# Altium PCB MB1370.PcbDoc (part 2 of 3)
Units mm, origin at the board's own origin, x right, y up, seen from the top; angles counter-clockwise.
Board outline 166 x 117 mm, 4 copper layers (Top Layer, Signal Layer 1, Signal Layer 2, Bottom Layer), stack 1.614 mm thick; 79 components, 100 nets, 342 pads, 822 vias.
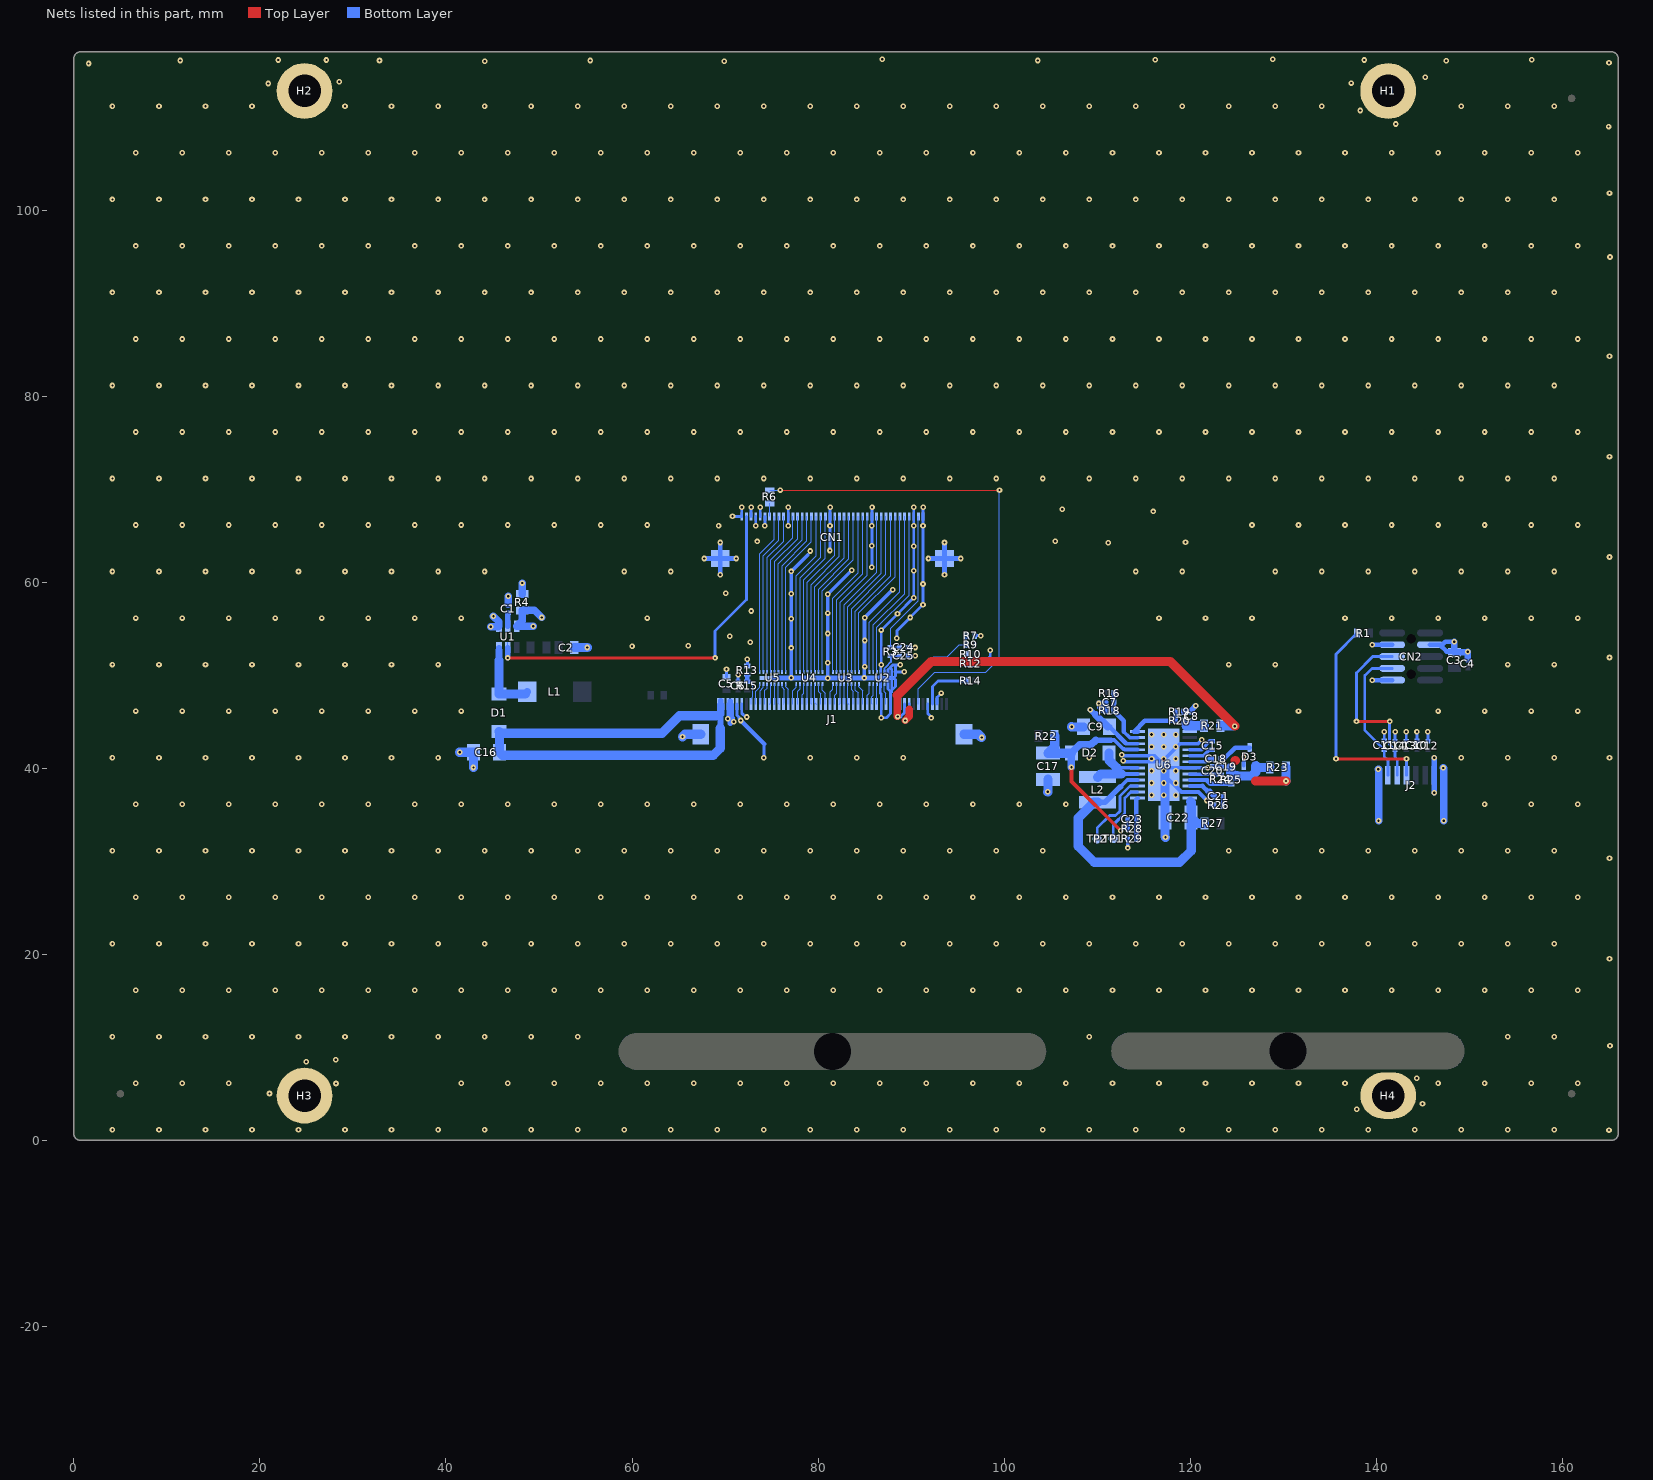
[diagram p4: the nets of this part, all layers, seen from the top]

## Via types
v1: diameter 0.6, hole 0.254, Top Layer to Bottom Layer, tented both sides, 804 vias
v2: diameter 0.6, hole 0.3, Top Layer to Bottom Layer, tented both sides, 18 vias

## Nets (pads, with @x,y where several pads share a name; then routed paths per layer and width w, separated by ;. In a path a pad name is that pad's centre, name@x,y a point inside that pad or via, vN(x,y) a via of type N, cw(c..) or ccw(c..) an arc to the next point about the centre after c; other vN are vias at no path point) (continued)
GND: C1.1 C2.1 C3.1 C4.2 C5.1 C6.1 C7.1 C8.1 C9.1 C10.1 C11.1 C12.1 C13.1 C14.1 C16.1 C17.1 C19.1 C20.1 C22.1 C24.1 C25.1 CN1.1 CN1.3 CN1.12 CN1.21 CN1.30 CN1.35 CN1.36 CN1.37 CN1.38 CN1.40 CN1.MT1 CN1.MT2 CN2.1 CN2.7 CN2.8 D3.2 H1.1 H2.1 H3.1 H4.1 J1.3 J1.13 J1.15 J1.46 J1.MT1 J1.MT2 J2.1 J2.MT1 J2.MT2 R4.1 R7.2 R12.2 R13.1 R18.1 R19.1 R26.1 R29.1 U1.4 U2.4 U2.6 U2.7 U2.8 U2.9 U2.10 U2.11 U2.13 U2.EP U3.EP U4.EP U5.EP U6.7 U6.8 U6.15 U6.19 U6.23 U6.EP | length 244.3
  Bottom Layer w0.3: v1@41.45,41.725 v1(41.461,41.714) ; C5.1@70.15,49.789 v1(70.15,50.65) ; v1(70.802,67.073) 70.812,67.063 CN1.40@71.79,67.063 71.79,68.04 v1(71.8,68.05) ; J1.46@71.29,46.889 71.29,45.685 71.5,45.475 71.5,45.3 v1(71.675,45.125) ; v1@71.375,50.075 v1(71.4,50.05) C6.1@71.4,49.289 ; R13.1@72.4,50.989 v1(72.4,51.725) ; CN1.38@72.79,67.063 72.79,68.04 v1(72.8,68.05) ; v1(73.28,66.075) 73.29,66.085 CN1.37@73.29,67.063 ; CN1.36@73.79,67.063 73.79,68.04 v1(73.8,68.05) ; v1@74.2,41.1 74.2,42.6 ; v1(74.28,66.075) 74.29,66.085 CN1.35@74.29,67.063 ; v1(76.78,66.075) 76.79,66.085 CN1.30@76.79,67.063 76.79,68.04 v1(76.8,68.05) ; v1(81.275,63.4) 81.28,63.405 v1(81.28,66.075) 81.29,66.085 CN1.21@81.29,67.063 81.29,68.04 v1(81.3,68.05) ; v1(85.775,61.6) 85.78,61.605 v1(85.78,66.075) 85.79,66.085 CN1.12@85.79,67.063 85.79,68.04 v1(85.8,68.05) ; U2.7@87.941,50.365 U2.7@87.925,50.349 ; v1(88.475,53.95) 88.475,54.775 v1(91.28,57.58) v1(91.28,66.075) 91.29,66.085 CN1.1@91.29,67.063 91.29,68.04 v1(91.3,68.05) ; v1(88.85,51.1) 88.4,51.1 ; v1(89.275,50.35) v1(89.275,50.35) U2.8@88.325,50.349 ; C25.1@89.65,52.075 v1(90.45,52.075) ; C24.1@89.65,52.975 v1(90.45,52.975) ; v1(90.3,68.05) 90.29,68.04 CN1.3@90.29,67.063 90.29,66.085 v1(90.28,66.075) v1(90.28,58.33) v1(88.54,56.59) v1(86.8,54.85) v1(86.8,51.125) 86.725,51.05 U2.4@86.725,50.349 86.725,49.899 U2.EP@86.925,49.699 ; J1.3@92.79,46.889 92.79,47.615 v1(93.25,48.075) ; R12.2@96.85,51.25 97.75,51.25 98.5,52 v1(98.5,52.675) ; R7.2@96.85,54.25 v1(97.5,54.25) ; C11.1@140.85,42.91 v1(140.85,43.925) ; C14.1@142.025,42.885 v1(142.025,43.9) ; C13.1@143.225,42.885 v1(143.225,43.9) ; C10.1@144.375,42.91 v1(144.375,43.925) ; C12.1@145.55,42.885 v1(145.55,43.9) ; U2.EP@86.925,49.699 86.725,49.499 U2.13@86.725,49.049 86.695,49.019 86.695,48.692 86.675,48.692 86.675,48.075 86.79,47.96 J1.15@86.79,46.889 86.79,45.435 v1(86.8,45.425) 87.35,45.425 87.79,45.865 J1.13@87.79,46.889 87.79,48.075 ; U2.EP@86.925,49.699 U2.EP@87.4,49.699 ; U2.EP@87.4,49.699 87.525,49.824 U2.6@87.525,50.349 87.525,50.591 87.72,50.786 ; U2.EP@87.4,49.699 U2.EP@87.476,49.699 ; U2.EP@87.476,49.699 87.525,49.65 U2.11@87.525,49.049 87.525,48.525 87.79,48.26 ; U2.EP@87.476,49.699 U2.EP@87.776,49.699 ; 87.72,50.786 87.925,50.581 U2.7@87.925,50.349 ; 87.72,50.786 87.72,50.795 88.025,51.1 88.4,51.1 ; U2.EP@87.776,49.699 87.925,49.55 U2.10@87.925,49.049 87.925,48.395 ; U2.EP@87.776,49.699 U2.EP@87.799,49.699 ; 87.79,48.075 87.925,48.21 87.925,48.395 ; 87.79,48.075 87.79,48.26 ; 87.79,48.26 87.925,48.395 ; U2.EP@87.799,49.699 87.925,49.825 U2.7@87.925,50.349 ; U2.EP@87.799,49.699 U2.EP@88.125,49.699 ; 87.925,48.395 88.325,48.795 U2.9@88.325,49.049 88.325,49.499 U2.EP@88.125,49.699 ; U2.EP@88.125,49.699 88.325,49.899 U2.8@88.325,50.349 ; U2.8@88.325,50.349 88.325,51.025 88.4,51.1
  Bottom Layer w0.4: v1(77.125,49.725) v1(77.125,61.15) 78.9,62.925 ; v1(81.05,49.65) 81.05,49.699 v1(81.05,58.7) v1(83.625,61.275) ; v1(84.975,49.7) 84.975,50.9 v1(85,50.925) v1(85,56.175) v1(88.025,59.2) ; 110.2,46.5 110.541,46.159 R18.1@110.9,46.159 ; v1(112.65,41.45) 112.766,41.334 U6.8@114.35,41.334 116.175,41.334 U6.EP@116.825,40.684 ; v1(112.8,40.8) 112.916,40.684 U6.7@114.35,40.684 U6.EP@116.825,40.684 ; v1(113.3,31.425) R29.1@113.3,32.434 ; v1(121.25,43.05) 120.834,42.634 U6.15@119.95,42.634 118.916,42.634 117.15,40.868 U6.EP@117.15,40.359 ; R26.1@122.6,35.989 122.336,35.989 120.891,37.434 U6.23@119.95,37.434 119.059,37.434 117.3,39.193 117.15,39.343 v2(117.15,39.709) U6.EP@117.15,40.359 ; C19.1@123.425,40.175 123.416,40.184 C20.1@122.425,40.184 122.275,40.034 v1(121.9,40.034) U6.19@119.95,40.034 117.475,40.034 117.3,40.209 U6.EP@117.15,40.359 ; D3.2@125.75,40.259 v1(125.75,41.2) ; U6.EP@116.825,40.684 U6.EP@117.15,40.359
  Bottom Layer w0.5: v1(67.763,62.538) CN1.MT2@69.49,62.538 ; v1(69.49,60.81) CN1.MT2@69.49,62.538 ; v1(69.49,64.265) CN1.MT2@69.49,62.538 ; v1(71.218,62.538) CN1.MT2@69.49,62.538 ; v1(71.675,45.125) 74.2,42.6 ; U5.EP@75.125,49.699 U4.EP@79.058,49.699 81.05,49.699 U3.EP@82.992,49.699 U2.EP@86.925,49.699 ; v1(91.862,62.538) CN1.MT1@93.59,62.538 ; v1(93.59,60.81) CN1.MT1@93.59,62.538 ; v1(93.59,64.265) CN1.MT1@93.59,62.538 ; v1(95.317,62.538) CN1.MT1@93.59,62.538 ; v1(139.59,49.46) CN2.1@141.715,49.46 ; v1(139.59,53.27) CN2.7@141.715,53.27 ; CN2.8@145.785,53.27 CN2.8@146.83,53.27 ; C3.1@148.4,52.55 147.55,52.55 CN2.8@146.83,53.27 ; v1(148.4,53.575) 147.4,53.575 147.095,53.27 CN2.8@146.83,53.27
  Bottom Layer w0.6: v1(110.175,46.95) 110.525,46.95 110.9,46.575 ; R18.1@110.9,46.159 110.9,46.575 ; C7.1@110.9,47.109 110.9,46.575 ; R19.1@119.325,46.084 120.1,46.084 C8.1@120.175,46.009 120.175,46.3 v1(120.6,46.725) ; v1(146.25,37.35) J2.1@146.25,39.235 v1(146.25,41.125)
  Bottom Layer w0.7: v1(148.4,53.575) 148.4,52.55 C3.1@148.4,52.475 149.825,52.475 v1(149.85,52.5) C4.2@149.85,51.675
  Bottom Layer w0.8: v1(44.8,55.2) 45.636,55.2 U1.4@45.7,55.264 45.7,55.75 v1(45.1,56.35) ; C1.1@46.7,57.614 v1(46.7,58.475) ; R4.1@48.2,58.714 v1(48.2,59.9) ; v1(140.225,39.9) 140.25,39.875 J2.MT2@140.25,37.135 v1(140.25,34.35) v1@140.275,34.325 ; v1(147.2,40.025) 147.25,39.975 J2.MT1@147.25,37.135 v1(147.25,34.35)
  Bottom Layer w1: v1(41.461,41.714) C16.1@42.95,41.714 v1(42.95,40.075) ; C2.1@53.8,52.964 55.189,52.964 v1(55.2,52.975) ; v1(65.425,43.375) 65.689,43.639 J1.MT1@67.39,43.639 ; J1.MT2@95.69,43.639 97.236,43.639 v1(97.575,43.3) ; v1(104.7,37.45) 104.725,37.475 C17.1@104.725,38.809 ; v1(107.25,44.45) 107.266,44.434 C9.1@108.525,44.434 ; U6.EP@117.3,40.209 117.3,39.193 C22.1@117.3,34.684 117.3,32.625 v1(117.35,32.575)
  other v1: 165.025,1.1 4.145,1.14 9.145,1.14 14.145,1.14 19.145,1.14 24.145,1.14 29.145,1.14 34.145,1.14 39.145,1.14 44.145,1.14 49.145,1.14 54.145,1.14 59.145,1.14 64.145,1.14 69.145,1.14 74.145,1.14 79.145,1.14 84.145,1.14 89.145,1.14 94.145,1.14 99.145,1.14 104.145,1.14 109.145,1.14 114.145,1.14 119.145,1.14 124.145,1.14 129.145,1.14 134.145,1.14 139.145,1.14 144.145,1.14 149.145,1.14 154.145,1.14 159.145,1.14 137.9,3.35 144.975,3.925 21.025,5.025 28.175,6.1 6.645,6.14 11.645,6.14 16.645,6.14 41.645,6.14 46.645,6.14 51.645,6.14 56.645,6.14 61.645,6.14 66.645,6.14 71.645,6.14 76.645,6.14 81.645,6.14 86.645,6.14 91.645,6.14 96.645,6.14 101.645,6.14 106.645,6.14 111.645,6.14 116.645,6.14 121.645,6.14 126.645,6.14 131.645,6.14 136.645,6.14 146.645,6.14 151.645,6.14 156.645,6.14 161.645,6.14 144.35,6.65 24.975,8.45 28.15,8.65 165.125,10.175 4.145,11.14 9.145,11.14 14.145,11.14 19.145,11.14 24.145,11.14 29.145,11.14 34.145,11.14 39.145,11.14 44.145,11.14 49.145,11.14 54.145,11.14 109.145,11.14 154.145,11.14 159.145,11.14 6.645,16.14 11.645,16.14 16.645,16.14 21.645,16.14 26.645,16.14 31.645,16.14 36.645,16.14 41.645,16.14 46.645,16.14 51.645,16.14 56.645,16.14 61.645,16.14 66.645,16.14 71.645,16.14 76.645,16.14 81.645,16.14 86.645,16.14 91.645,16.14 96.645,16.14 101.645,16.14 106.645,16.14 111.645,16.14 116.645,16.14 121.645,16.14 126.645,16.14 131.645,16.14 136.645,16.14 141.645,16.14 146.645,16.14 151.645,16.14 156.645,16.14 161.645,16.14 165.075,19.525 4.145,21.14 9.145,21.14 14.145,21.14 19.145,21.14 24.145,21.14 29.145,21.14 34.145,21.14 39.145,21.14 44.145,21.14 49.145,21.14 54.145,21.14 59.145,21.14 64.145,21.14 69.145,21.14 74.145,21.14 79.145,21.14 84.145,21.14 89.145,21.14 94.145,21.14 99.145,21.14 104.145,21.14 109.145,21.14 114.145,21.14 119.145,21.14 124.145,21.14 129.145,21.14 134.145,21.14 139.145,21.14 144.145,21.14 149.145,21.14 154.145,21.14 159.145,21.14 6.645,26.14 11.645,26.14 16.645,26.14 21.645,26.14 26.645,26.14 31.645,26.14 36.645,26.14 41.645,26.14 46.645,26.14 51.645,26.14 56.645,26.14 61.645,26.14 66.645,26.14 71.645,26.14 76.645,26.14 81.645,26.14 86.645,26.14 91.645,26.14 96.645,26.14 101.645,26.14 106.645,26.14 111.645,26.14 116.645,26.14 121.645,26.14 126.645,26.14 131.645,26.14 136.645,26.14 141.645,26.14 146.645,26.14 151.645,26.14 156.645,26.14 161.645,26.14 165.075,30.325 4.145,31.14 9.145,31.14 14.145,31.14 19.145,31.14 24.145,31.14 29.145,31.14 34.145,31.14 39.145,31.14 44.145,31.14 49.145,31.14 54.145,31.14 59.145,31.14 64.145,31.14 69.145,31.14 74.145,31.14 79.145,31.14 84.145,31.14 89.145,31.14 94.145,31.14 99.145,31.14 104.145,31.14 124.145,31.14 129.145,31.14 134.145,31.14 139.145,31.14 144.145,31.14 149.145,31.14 154.145,31.14 159.145,31.14 6.645,36.14 11.645,36.14 16.645,36.14 21.645,36.14 26.645,36.14 31.645,36.14 36.645,36.14 41.645,36.14 46.645,36.14 51.645,36.14 56.645,36.14 61.645,36.14 66.645,36.14 71.645,36.14 76.645,36.14 81.645,36.14 86.645,36.14 91.645,36.14 96.645,36.14 101.645,36.14 106.645,36.14 151.645,36.14 156.645,36.14 161.645,36.14 121.775,36.525 4.145,41.14 9.145,41.14 14.145,41.14 19.145,41.14 24.145,41.14 29.145,41.14 34.145,41.14 39.145,41.14 74.145,41.14 79.145,41.14 84.145,41.14 89.145,41.14 109.145,41.14 149.145,41.14 154.145,41.14 159.145,41.14 165.075,41.125 6.645,46.14 11.645,46.14 16.645,46.14 21.645,46.14 26.645,46.14 31.645,46.14 36.645,46.14 41.645,46.14 131.645,46.14 146.645,46.14 151.645,46.14 156.645,46.14 161.645,46.14 4.145,51.14 9.145,51.14 14.145,51.14 19.145,51.14 24.145,51.14 29.145,51.14 34.145,51.14 39.145,51.14 124.145,51.14 129.145,51.14 154.145,51.14 159.145,51.14 81.05,51.35 165.075,51.9 77.125,52.925 60,53.1 66.05,53.175 72.725,53.55 85,53.725 70.5,54.2 81.05,54.475 77.125,56.075 6.645,56.14 11.645,56.14 16.645,56.14 21.645,56.14 26.645,56.14 31.645,56.14 36.645,56.14 41.645,56.14 61.645,56.14 116.645,56.14 121.645,56.14 126.645,56.14 136.645,56.14 141.645,56.14 146.645,56.14 151.645,56.14 156.645,56.14 161.645,56.14 89.9,56.2 81.05,56.675 72.825,56.9 77.125,58.75 70.075,58.8 91.28,59.8 4.145,61.14 9.145,61.14 14.145,61.14 19.145,61.14 24.145,61.14 29.145,61.14 34.145,61.14 39.145,61.14 44.145,61.14 59.145,61.14 64.145,61.14 114.145,61.14 119.145,61.14 129.145,61.14 134.145,61.14 139.145,61.14 144.145,61.14 149.145,61.14 154.145,61.14 159.145,61.14 90.28,61.225 165.075,62.7 79.175,63.35 90.28,63.875 85.78,63.925 111.175,64.225 119.5,64.3 73.45,64.375 105.475,64.4 69.3,66.075 6.645,66.14 11.645,66.14 16.645,66.14 21.645,66.14 26.645,66.14 31.645,66.14 36.645,66.14 41.645,66.14 46.645,66.14 51.645,66.14 56.645,66.14 61.645,66.14 126.645,66.14 131.645,66.14 136.645,66.14 141.645,66.14 146.645,66.14 151.645,66.14 156.645,66.14 161.645,66.14 116.025,67.6 106.25,67.85 4.145,71.14 9.145,71.14 14.145,71.14 19.145,71.14 24.145,71.14 29.145,71.14 34.145,71.14 39.145,71.14 44.145,71.14 49.145,71.14 54.145,71.14 59.145,71.14 64.145,71.14 69.145,71.14 74.145,71.14 79.145,71.14 84.145,71.14 89.145,71.14 94.145,71.14 99.145,71.14 104.145,71.14 109.145,71.14 114.145,71.14 119.145,71.14 124.145,71.14 129.145,71.14 134.145,71.14 139.145,71.14 144.145,71.14 149.145,71.14 154.145,71.14 159.145,71.14 165.075,73.5 6.645,76.14 11.645,76.14 16.645,76.14 21.645,76.14 26.645,76.14 31.645,76.14 36.645,76.14 41.645,76.14 46.645,76.14 51.645,76.14 56.645,76.14 61.645,76.14 66.645,76.14 71.645,76.14 76.645,76.14 81.645,76.14 86.645,76.14 91.645,76.14 96.645,76.14 101.645,76.14 106.645,76.14 111.645,76.14 116.645,76.14 121.645,76.14 126.645,76.14 131.645,76.14 136.645,76.14 141.645,76.14 146.645,76.14 151.645,76.14 156.645,76.14 161.645,76.14 4.145,81.14 9.145,81.14 14.145,81.14 19.145,81.14 24.145,81.14 29.145,81.14 34.145,81.14 39.145,81.14 44.145,81.14 49.145,81.14 54.145,81.14 59.145,81.14 64.145,81.14 69.145,81.14 74.145,81.14 79.145,81.14 84.145,81.14 89.145,81.14 94.145,81.14 99.145,81.14 104.145,81.14 109.145,81.14 114.145,81.14 119.145,81.14 124.145,81.14 129.145,81.14 134.145,81.14 139.145,81.14 144.145,81.14 149.145,81.14 154.145,81.14 159.145,81.14 165.075,84.3 6.645,86.14 11.645,86.14 16.645,86.14 21.645,86.14 26.645,86.14 31.645,86.14 36.645,86.14 41.645,86.14 46.645,86.14 51.645,86.14 56.645,86.14 61.645,86.14 66.645,86.14 71.645,86.14 76.645,86.14 81.645,86.14 86.645,86.14 91.645,86.14 96.645,86.14 101.645,86.14 106.645,86.14 111.645,86.14 116.645,86.14 121.645,86.14 126.645,86.14 131.645,86.14 136.645,86.14 141.645,86.14 146.645,86.14 151.645,86.14 156.645,86.14 161.645,86.14 4.145,91.14 9.145,91.14 14.145,91.14 19.145,91.14 24.145,91.14 29.145,91.14 34.145,91.14 39.145,91.14 44.145,91.14 49.145,91.14 54.145,91.14 59.145,91.14 64.145,91.14 69.145,91.14 74.145,91.14 79.145,91.14 84.145,91.14 89.145,91.14 94.145,91.14 99.145,91.14 104.145,91.14 109.145,91.14 114.145,91.14 119.145,91.14 124.145,91.14 129.145,91.14 134.145,91.14 139.145,91.14 144.145,91.14 149.145,91.14 154.145,91.14 159.145,91.14 165.125,94.95 6.645,96.14 11.645,96.14 16.645,96.14 21.645,96.14 26.645,96.14 31.645,96.14 36.645,96.14 41.645,96.14 46.645,96.14 51.645,96.14 56.645,96.14 61.645,96.14 66.645,96.14 71.645,96.14 76.645,96.14 81.645,96.14 86.645,96.14 91.645,96.14 96.645,96.14 101.645,96.14 106.645,96.14 111.645,96.14 116.645,96.14 121.645,96.14 126.645,96.14 131.645,96.14 136.645,96.14 141.645,96.14 146.645,96.14 151.645,96.14 156.645,96.14 161.645,96.14 4.145,101.14 9.145,101.14 14.145,101.14 19.145,101.14 24.145,101.14 29.145,101.14 34.145,101.14 39.145,101.14 44.145,101.14 49.145,101.14 54.145,101.14 59.145,101.14 64.145,101.14 69.145,101.14 74.145,101.14 79.145,101.14 84.145,101.14 89.145,101.14 94.145,101.14 99.145,101.14 104.145,101.14 109.145,101.14 114.145,101.14 119.145,101.14 124.145,101.14 129.145,101.14 134.145,101.14 139.145,101.14 144.145,101.14 149.145,101.14 154.145,101.14 159.145,101.14 165.075,101.825 6.645,106.14 11.645,106.14 16.645,106.14 21.645,106.14 26.645,106.14 31.645,106.14 36.645,106.14 41.645,106.14 46.645,106.14 51.645,106.14 56.645,106.14 61.645,106.14 66.645,106.14 71.645,106.14 76.645,106.14 81.645,106.14 86.645,106.14 91.645,106.14 96.645,106.14 101.645,106.14 106.645,106.14 111.645,106.14 116.645,106.14 121.645,106.14 126.645,106.14 131.645,106.14 136.645,106.14 141.645,106.14 146.645,106.14 151.645,106.14 156.645,106.14 161.645,106.14 164.975,108.975 142.1,109.25 138.275,110.7 4.145,111.14 9.145,111.14 14.145,111.14 19.145,111.14 29.145,111.14 34.145,111.14 39.145,111.14 44.145,111.14 49.145,111.14 54.145,111.14 59.145,111.14 64.145,111.14 69.145,111.14 74.145,111.14 79.145,111.14 84.145,111.14 89.145,111.14 94.145,111.14 99.145,111.14 104.145,111.14 109.145,111.14 114.145,111.14 119.145,111.14 124.145,111.14 129.145,111.14 134.145,111.14 149.145,111.14 154.145,111.14 159.145,111.14 20.875,113.6 137.325,113.65 28.525,113.8 145.25,114.275 1.575,115.75 165.025,115.85 44.175,116 69.9,116 147.525,116.05 11.45,116.075 32.85,116.075 55.525,116.075 103.6,116.075 21.975,116.125 27.15,116.125 138.725,116.125 116.225,116.175 156.7,116.175 86.9,116.225 128.875,116.225
  other v2: 115.85,37.109 117.15,37.109 118.45,37.109 115.85,38.409 117.15,38.409 118.45,38.409 115.85,39.709 118.45,39.709 115.85,41.009 117.15,41.009 118.45,41.009 115.85,42.309 117.15,42.309 118.45,42.309 115.85,43.609 117.15,43.609 118.45,43.609
I2C_SCL: C14.2 CN2.5 J2.5 | length 19.5
  Top Layer w0.3: v1(137.875,45.025) v1(141.45,45.025)
  Bottom Layer w0.3: v1(137.875,45.025) 137.875,50.25 139.625,52 CN2.5@141.715,52 ; v1(141.45,45.025) 141.433,45.008 141.433,42.543 141.991,41.985 142.008,41.985 142.008,41.192 142.25,40.95 J2.5@142.25,39.235
I2C_SDA: C11.2 CN2.3 J2.6 | length 15
  Bottom Layer w0.3: J2.6@141.25,39.235 141.25,40.85 140.85,41.25 C11.2@140.85,42.01 140.833,42.01 138.775,44.068 138.775,49.975 139.53,50.73 CN2.3@141.715,50.73
LCD1_B0: J1.32 U4.14 | length 2.2
  Bottom Layer w0.12: J1.32@78.29,46.889 78.29,47.873 78.458,48.042 U4.14@78.458,49.049
LCD1_B1: J1.33 U4.15 | length 2.3
  Bottom Layer w0.12: J1.33@77.79,46.889 77.79,48.29 78.058,48.558 U4.15@78.058,49.049
LCD1_B2: J1.34 U4.16 | length 2.3
  Bottom Layer w0.12: J1.34@77.29,46.889 77.29,48.34 77.658,48.708 U4.16@77.658,49.049
LCD1_B3: J1.35 U5.9 | length 2.3
  Bottom Layer w0.12: U5.9@76.525,49.049 76.525,48.775 76.79,48.51 J1.35@76.79,46.889
LCD1_B4: J1.36 U5.10 | length 2.3
  Bottom Layer w0.12: U5.10@76.125,49.049 76.125,48.675 76.375,48.425 76.375,46.974 J1.36@76.29,46.889
LCD1_B5: J1.37 U5.11 | length 2.2
  Bottom Layer w0.12: U5.11@75.725,49.049 75.725,46.954 J1.37@75.79,46.889
LCD1_B6: J1.38 U5.12 | length 2.2
  Bottom Layer w0.12: J1.38@75.29,46.889 75.325,46.924 U5.12@75.325,49.049
LCD1_B7: J1.39 U5.13 | length 2.2
  Bottom Layer w0.12: J1.39@74.79,46.889 74.925,47.024 U5.13@74.925,49.049
LCD1_DCLK: J1.14 U2.12 | length 2.2
  Bottom Layer w0.12: U2.12@87.125,49.049 87.125,48.225 87.29,48.06 J1.14@87.29,46.889
LCD1_DE: J1.42 U5.16 | length 2.3
  Bottom Layer w0.12: J1.42@73.29,46.889 73.29,48.265 73.725,48.7 U5.16@73.725,49.049
LCD1_DITHB: J1.4 R14.2 | length 5.8
  Bottom Layer w0.3: J1.4@92.29,46.889 92.29,48.79 92.875,49.375 R14.2@95.95,49.375
LCD1_G0: J1.24 U3.14 | length 2.2
  Bottom Layer w0.12: J1.24@82.29,46.889 82.392,46.991 U3.14@82.392,49.049
LCD1_G1: J1.25 U3.15 | length 2.2
  Bottom Layer w0.12: J1.25@81.79,46.889 81.79,47.84 81.992,48.042 U3.15@81.992,49.049
LCD1_G2: J1.26 U3.16 | length 2.3
  Bottom Layer w0.12: J1.26@81.29,46.889 81.29,48.19 81.592,48.492 U3.16@81.592,49.049
LCD1_G3: J1.27 U4.9 | length 2.3
  Bottom Layer w0.12: U4.9@80.458,49.049 80.458,48.367 80.79,48.035 J1.27@80.79,46.889
LCD1_G4: J1.28 U4.10 | length 2.3
  Bottom Layer w0.12: U4.10@80.058,49.049 80.058,48.242 80.29,48.01 J1.28@80.29,46.889
LCD1_G5: J1.29 U4.11 | length 2.2
  Bottom Layer w0.12: U4.11@79.658,49.049 79.658,47.021 J1.29@79.79,46.889
LCD1_G6: J1.30 U4.12 | length 2.2
  Bottom Layer w0.12: U4.12@79.258,49.049 79.258,46.921 J1.30@79.29,46.889
LCD1_G7: J1.31 U4.13 | length 2.2
  Bottom Layer w0.12: J1.31@78.79,46.889 78.858,46.957 U4.13@78.858,49.049
LCD1_HSYNC: J1.40 U5.14 | length 2.3
  Bottom Layer w0.12: J1.40@74.29,46.889 74.29,48.365 74.525,48.6 U5.14@74.525,49.049
LCD1_MODE: J1.43 R13.2 R15.1 | length 3.7
  Bottom Layer w0.13: R15.1@72.4,49.289 72.761,49.289 73,49.05 73,47.661 72.79,47.451 J1.43@72.79,46.889
  Bottom Layer w0.5: R15.1@72.4,49.289 R13.2@72.4,50.089
LCD1_R0: J1.16 U2.14 | length 2.2
  Bottom Layer w0.12: J1.16@86.29,46.889 86.325,46.924 U2.14@86.325,49.049
LCD1_R1: J1.17 U2.15 | length 2.2
  Bottom Layer w0.12: J1.17@85.79,46.889 85.75,46.929 85.75,47.675 85.925,47.85 U2.15@85.925,49.049
LCD1_R2: J1.18 U2.16 | length 2.3
  Bottom Layer w0.12: J1.18@85.29,46.889 85.29,47.84 85.525,48.075 U2.16@85.525,49.049
LCD1_R3: J1.19 U3.9 | length 2.3
  Bottom Layer w0.12: U3.9@84.392,49.049 84.392,48.733 84.79,48.335 J1.19@84.79,46.889
LCD1_R4: J1.20 U3.10 | length 2.3
  Bottom Layer w0.12: U3.10@83.992,49.049 83.992,48.383 84.29,48.085 J1.20@84.29,46.889
LCD1_R5: J1.21 U3.11 | length 2.2
  Bottom Layer w0.12: U3.11@83.592,49.049 83.592,48.433 83.79,48.235 J1.21@83.79,46.889
LCD1_R6: J1.22 U3.12 | length 2.2
  Bottom Layer w0.12: U3.12@83.192,49.049 83.192,46.987 J1.22@83.29,46.889
LCD1_R7: J1.23 U3.13 | length 2.2
  Bottom Layer w0.12: J1.23@82.79,46.889 82.792,46.891 U3.13@82.792,49.049
LCD1_VSYNC: J1.41 U5.15 | length 2.3
  Bottom Layer w0.12: J1.41@73.79,46.889 73.79,48.34 74.125,48.675 U5.15@74.125,49.049
LCD_B0: CN1.22 U4.3 | length 17.7
  Bottom Layer w0.12: U4.3@78.458,50.349 78.458,60.233 80.79,62.565 CN1.22@80.79,67.063
LCD_B1: CN1.23 U4.2 | length 17.6
  Bottom Layer w0.12: U4.2@78.058,50.349 78.058,60.458 80.29,62.69 CN1.23@80.29,67.063
LCD_B2: CN1.24 U4.1 | length 17.6
  Bottom Layer w0.12: U4.1@77.658,50.349 77.658,60.708 79.79,62.84 CN1.24@79.79,67.063
LCD_B3: CN1.25 U5.8 | length 17.9
  Bottom Layer w0.12: U5.8@76.525,50.349 76.525,61.575 79.29,64.34 CN1.25@79.29,67.063
LCD_B4: CN1.26 U5.7 | length 17.8
  Bottom Layer w0.12: U5.7@76.125,50.349 76.125,61.775 78.79,64.44 CN1.26@78.79,67.063
LCD_B5: CN1.27 U5.6 | length 17.8
  Bottom Layer w0.12: U5.6@75.725,50.349 75.725,62 78.29,64.565 CN1.27@78.29,67.063
LCD_B6: CN1.28 U5.5 | length 17.7
  Bottom Layer w0.12: U5.5@75.325,50.349 75.325,62.225 77.79,64.69 CN1.28@77.79,67.063
LCD_B7: CN1.29 U5.4 | length 17.7
  Bottom Layer w0.12: U5.4@74.925,50.349 74.925,62.425 77.29,64.79 CN1.29@77.29,67.063
LCD_BL_CTRL: CN1.39 U1.2 | length 40.6
  Top Layer w0.3: v1(46.65,51.85) v1(68.925,51.85)
  Bottom Layer w0.12: U1.2@46.65,52.964 U1.2@46.65,53.525
  Bottom Layer w0.3: v1(68.925,51.85) 68.925,54.75 72.29,58.115 CN1.39@72.29,67.063
  Bottom Layer w0.6: v1(46.65,51.85) U1.2@46.65,52.964
LCD_CLK: C24.2 CN1.2 R3.1 | length 16.2
  Bottom Layer w0.12: R3.1@87.825,52.975 87.825,55.025 90.79,57.99 CN1.2@90.79,67.063
  Bottom Layer w0.2: R3.1@87.825,52.975 C24.2@88.75,52.975
LCD_CLK_CN: C25.2 R3.2 U2.5 | length 2.9
  Bottom Layer w0.2: U2.5@87.125,50.349 87.125,50.715 87.32,50.91 87.32,50.918 87.825,51.423 R3.2@87.825,52.075 C25.2@88.75,52.075
LCD_DE: CN1.33 U5.1 | length 17.4
  Bottom Layer w0.12: U5.1@73.725,50.349 73.725,63.025 75.29,64.59 CN1.33@75.29,67.063
LCD_G0: CN1.13 U3.3 | length 17.9
  Bottom Layer w0.12: U3.3@82.392,50.349 82.392,57.817 85.29,60.715 CN1.13@85.29,67.063
LCD_G1: CN1.14 U3.2 | length 17.9
  Bottom Layer w0.12: U3.2@81.992,50.349 81.992,58.092 84.79,60.89 CN1.14@84.79,67.063
LCD_G2: CN1.15 U3.1 | length 17.8
  Bottom Layer w0.12: U3.1@81.592,50.349 81.592,58.292 84.29,60.99 CN1.15@84.29,67.063
LCD_G3: CN1.16 U4.8 | length 18.1
  Bottom Layer w0.12: U4.8@80.458,50.349 80.458,59.058 83.79,62.39 CN1.16@83.79,67.063
LCD_G4: CN1.17 U4.7 | length 18.1
  Bottom Layer w0.12: U4.7@80.058,50.349 80.058,59.258 83.29,62.49 CN1.17@83.29,67.063
LCD_G5: CN1.18 U4.6 | length 18
  Bottom Layer w0.12: U4.6@79.658,50.349 79.658,59.483 82.79,62.615 CN1.18@82.79,67.063
LCD_G6: CN1.19 U4.5 | length 18
  Bottom Layer w0.12: U4.5@79.258,50.349 79.258,59.733 82.29,62.765 CN1.19@82.29,67.063
LCD_G7: CN1.20 U4.4 | length 17.9
  Bottom Layer w0.12: U4.4@78.858,50.349 78.858,59.983 81.79,62.915 CN1.20@81.79,67.063
LCD_HSYNC: CN1.31 U5.3 | length 17.4
  Bottom Layer w0.12: U5.3@74.525,50.349 74.525,62.65 76.29,64.415 CN1.31@76.29,67.063
LCD_R0: CN1.4 U2.3 | length 18.2
  Bottom Layer w0.12: U2.3@86.325,50.349 86.32,50.354 86.32,55.145 89.79,58.615 CN1.4@89.79,67.063
LCD_R1: CN1.5 U2.2 | length 18.1
  Bottom Layer w0.12: U2.2@85.925,50.349 85.925,55.4 89.29,58.765 CN1.5@89.29,67.063
LCD_R2: CN1.6 U2.1 | length 18.1
  Bottom Layer w0.12: U2.1@85.525,50.349 85.525,55.675 88.79,58.94 CN1.6@88.79,67.063
LCD_R3: CN1.7 U3.8 | length 18.3
  Bottom Layer w0.12: U3.8@84.392,50.349 84.392,56.692 88.29,60.59 CN1.7@88.29,67.063
LCD_R4: CN1.8 U3.7 | length 18.3
  Bottom Layer w0.12: U3.7@83.992,50.349 83.992,56.892 87.79,60.69 CN1.8@87.79,67.063
LCD_R5: CN1.9 U3.6 | length 18.2
  Bottom Layer w0.12: U3.6@83.592,50.349 83.592,57.142 87.29,60.84 CN1.9@87.29,67.063
LCD_R6: CN1.10 U3.5 | length 18.2
  Bottom Layer w0.12: U3.5@83.192,50.349 83.192,57.342 86.79,60.94 CN1.10@86.79,67.063
LCD_R7: CN1.11 U3.4 | length 18.2
  Bottom Layer w0.12: U3.4@82.792,50.349 82.792,57.567 86.29,61.065 CN1.11@86.29,67.063
LCD_RESET: CN1.34 R6.1 | length 1.4
  Bottom Layer w0.12: CN1.34@74.79,67.063 74.79,68.465 R6.1@74.8,68.475
LCD_VSYNC: CN1.32 U5.2 | length 17.4
  Bottom Layer w0.12: U5.2@74.125,50.349 74.125,62.85 75.79,64.515 CN1.32@75.79,67.063
LR: J1.12 R7.1 R9.1 | length 11.9
  Bottom Layer w0.12: J1.12@88.29,46.889 88.29,47.865 92.425,52 93.9,52 95.15,53.25 R9.1@95.95,53.25 R7.1@95.95,54.25
NetC1_2: C1.2 U1.5 | length 1.5
  Bottom Layer w0.6: U1.5@46.65,55.264 46.65,56.664 C1.2@46.7,56.714
NetC7_2: C7.2 R16.2 R18.2 U6.11 | length 6.3
  Bottom Layer w0.4: 112.85,43.925 113.491,43.284 U6.11@114.35,43.284
  Bottom Layer w0.5: R16.2@111.8,48.059 C7.2@111.8,47.109 R18.2@111.8,46.159 112.85,45.109 112.85,43.925
NetC8_2: C8.2 R20.2 R21.1 U6.13 | length 3.1
  Bottom Layer w0.5: R20.2@119.325,45.084 119.325,44.8 119.55,44.575 ; 120.1,44.559 120.175,44.634 C8.2@120.175,45.109
  Bottom Layer w1: 119.55,44.575 119.566,44.559 120.1,44.559 R21.1@121.5,44.559
NetC15_1: C15.1 U6.16 | length 2.8
  Bottom Layer w0.4: U6.16@119.95,41.984 121.209,41.984 122.109,42.884
  Bottom Layer w0.5: 122.109,42.884 C15.1@122.4,42.884
NetC15_2: C15.2 U6.17 | length 2.7
  Bottom Layer w0.4: U6.17@119.95,41.334 121.436,41.334 122.086,41.984
  Bottom Layer w0.5: 122.086,41.984 C15.2@122.4,41.984
NetC17_2: C17.2 C23.2 D2.2 R22.1 R28.2 U6.9 | length 25.4
  Top Layer w0.4: v1(107.235,40.115) 107.235,38.58 v1(112.545,33.27)
  Bottom Layer w0.4: 111.45,43.024 111.848,43.024 112.802,42.07 112.907,42.07 112.963,42.014 114.35,42.014 U6.9@114.35,41.984 ; v1(112.545,33.27) 112.875,33.6 113.184,33.6 R28.2@113.3,33.484 ; C23.2@113.3,34.484 C23.2@113.34,34.524
  Bottom Layer w0.5: R28.2@113.3,33.484 C23.2@113.3,34.484
  Bottom Layer w0.6: 109.849,43.024 111.45,43.024
  Bottom Layer w0.8: v1(107.235,40.115) D2.2@107.235,41.634 108.101,42.5 109.325,42.5 109.849,43.024
  Bottom Layer w1: R22.1@105.425,43.459 105.425,42.309 C17.2@104.725,41.609 107.21,41.609 D2.2@107.235,41.634
NetC18_1: C18.1 U6.18 | length 2.6
  Bottom Layer w0.4: U6.18@119.95,40.684 121.663,40.684 121.988,41.009
  Bottom Layer w0.5: 121.988,41.009 C18.1@122.375,41.009
NetC18_2: C18.2 D3.3 | length 3.6
  Bottom Layer w0.5: C18.2@123.275,41.009 123.634,41.009 124.834,42.209 D3.3@126.4,42.209
NetC19_2: C19.2 D3.1 R23.2 R25.1 | length 6
  Bottom Layer w1: C19.2@124.35,40.084 124.35,39.284 R25.1@124.425,39.209 124.45,39.184 124.78,39.184 125.032,39.184 125.052,39.164 126.62,39.164 127.05,39.594 D3.1@127.05,40.259 127.225,40.084 R23.2@128.55,40.084
NetC20_2: C20.2 R24.2 U6.20 | length 3.3
  Bottom Layer w0.4: U6.20@119.98,39.354 C20.2@122.355,39.354
  Bottom Layer w0.5: C20.2@122.355,39.354 C20.2@122.425,39.284 R24.2@123.3,39.284
NetC21_1: C21.1 U6.22 | length 3.1
  Bottom Layer w0.4: U6.22@119.95,38.084 121.316,38.084
  Bottom Layer w0.5: 121.316,38.084 121.9,37.5
  Bottom Layer w0.6: 121.9,37.5 122.084,37.5 C21.1@122.625,36.959
NetC21_2: C21.2 R26.2 | length 1
  Bottom Layer w0.4: R26.2@123.5,35.989 123.5,36.934 C21.2@123.525,36.959
NetC22_2: C22.2 L2.1 R27.2 U6.4 U6.24 | length 31.9
  Bottom Layer w0.3: U6.24@119.95,36.784 120.025,36.709 120.025,36.4
  Bottom Layer w0.4: 112.525,38.025 113.234,38.734 U6.4@114.35,38.734
  Bottom Layer w0.6: L2.1@110.05,36.334 110.834,36.334 112.525,38.025
  Bottom Layer w1: L2.1@110.05,36.334 109.659,36.334 107.975,34.65 107.975,31.6 109.7,29.875 118.85,29.875 120.1,31.125 C22.2@120.1,34.684 ; 120.025,36.4 120.1,36.325 C22.2@120.1,34.684 ; R27.2@121.525,34.059 120.725,34.059 C22.2@120.1,34.684
NetC23_1: C23.1 R28.1 R29.2 U6.1 | length 4.4
  Bottom Layer w0.5: R29.2@114.2,32.434 R28.1@114.2,33.484 C23.1@114.2,34.484 114.2,36.634 U6.1@114.35,36.784
NetD2_1: D2.1 L2.2 U6.5 U6.6 | length 8.6
  Bottom Layer w0.4: 112.091,40.034 U6.6@114.35,40.034 ; 112.591,39.384 U6.5@114.35,39.384
  Bottom Layer w1: L2.2@110.05,39.034 110.4,39.384 112.591,39.384 ; D2.1@111.265,41.634 111.265,40.86 112.091,40.034
NetJ1_7: J1.7 R6.2 | length 54.5
  Top Layer w0.12: v1(75.925,69.9) v1(99.5,69.9)
  Bottom Layer w0.12: R6.2@74.8,69.875 75.9,69.875 v1(75.925,69.9) ; J1.7@90.79,46.889 90.79,48.54 92.55,50.3 98.025,50.3 99.5,51.775 v1(99.5,69.9)
NetJ2_4: J2.4 R1.2 | length 23.8
  Top Layer w0.3: v1(135.675,41) v1(143.25,41)
  Bottom Layer w0.3: v1(135.675,41) 135.675,52.25 R1.2@137.95,54.525 ; J2.4@143.25,39.235 v1(143.25,41)
NetR19_2: R19.2 R20.1 U6.12 | length 6.3
  Bottom Layer w0.5: U6.12@114.35,43.934 113.966,43.934 115.116,45.084 R20.1@118.425,45.084 R19.2@118.425,46.084
NetR24_1: R24.1 R25.2 U6.21 | length 4.7
  Bottom Layer w0.4: U6.21@119.95,38.734 121.859,38.734
  Bottom Layer w0.5: 121.801,38.676 122.164,38.314 124.42,38.314 R25.2@124.425,38.309
NetTP1_1: TP1.1 U6.2 | length 6.5
  Bottom Layer w0.3: TP1.1@111.725,32.434 111.725,33.925 112.975,35.175 112.975,36.8 113.609,37.434 U6.2@114.35,37.434
NetTP2_1: TP2.1 U6.3 | length 8.3
  Bottom Layer w0.3: TP2.1@110,32.409 110,33.55 111.35,34.9 111.975,34.9 112.45,35.375 112.45,37 113.534,38.084 U6.3@114.35,38.084
UD: J1.11 R10.1 R12.1 | length 11.1
  Bottom Layer w0.12: J1.11@88.79,46.285 J1.11@88.79,46.889 88.79,47.69 92.45,51.35 95.85,51.35 R12.1@95.95,51.25 R10.1@95.95,52.25
VCOM: C9.2 J1.5 J1.45 U6.10 | length 10
  Bottom Layer w0.3: J1.45@71.79,46.914 J1.45@71.79,46.889 71.79,45.91 72.2,45.5 v1(72.325,45.5) ; J1.5@91.79,46.889 91.79,45.885 92.175,45.5 v1(92.175,45.4)
  Bottom Layer w0.4: 113.069,42.69 113.164,42.69 113.22,42.634 U6.10@114.35,42.634
  Bottom Layer w0.5: C9.2@111.325,44.434 113.069,42.69
  Bottom Layer w0.6: v1(109.25,46.3) 109.825,45.725 ; C9.2@111.116,44.434 C9.2@111.325,44.434
  Bottom Layer w0.8: 109.825,45.725 C9.2@111.116,44.434
VGH: J1.10 R21.2 | length 46.1
  Top Layer w0.8: v1@88.524,45.601 88.524,47.849
  Top Layer w1: 88.524,47.849 92.15,51.475 117.85,51.475 v1(124.8,44.525)
  Bottom Layer w0.3: 88.875,45.55 89.29,45.965 J1.10@89.29,46.889
  Bottom Layer w0.4: v1(88.575,45.55) 88.875,45.55
  Bottom Layer w1: R21.2@123.25,44.559 124.591,44.559 v1@124.6,44.55
VGL: J1.9 R23.1 | length 8.1
  Top Layer w0.8: v1(89.35,45.125) 89.79,45.565 89.79,46.365
  Top Layer w1: 127.024,38.625 v1(130.3,38.625)
  Bottom Layer w0.3: v1(89.35,45.125) 89.79,45.565 J1.9@89.79,46.889
  Bottom Layer w1: v1(130.3,38.625) R23.1@130.3,40.084
VLED+: C16.2 D1.2 J1.49 J1.50 | length 59.5
  Bottom Layer w0.3: 69,45.625 69,45.85 69.29,46.14 J1.50@69.29,46.889 ; 69.475,45.4 69.525,45.45 69.79,45.715 J1.49@69.79,46.914
  Bottom Layer w0.6: 69.475,44.289 69.475,45.175 ; 69.525,44.289 69.525,45.45 69.525,47.25
  Bottom Layer w1: D1.2@45.7,43.949 D1.2@45.75,43.899 ; 69,45.625 65.1,45.625 63.225,43.75 45.899,43.75 D1.2@45.75,43.899 ; 69.475,44.289 69.475,42.15 68.725,41.4 46.064,41.4 C16.2@45.75,41.714 D1.2@45.75,43.899
VLED+_SW: D1.1 L1.1 U1.3 | length 8.1
  Bottom Layer w0.6: U1.3@45.7,52.7 U1.3@45.7,52.964
  Bottom Layer w0.8: 45.7,51.575 U1.3@45.7,52.7 ; L1.1@48.515,47.979 L1.1@48.75,48.214
  Bottom Layer w1: 45.7,51.575 D1.1@45.7,47.979 L1.1@48.515,47.979
VLED-: J1.47 J1.48 R4.2 U1.6 | length 12
  Bottom Layer w0.3: v1(70.29,45.3) J1.48@70.29,46.889 ; J1.47@70.79,46.889 70.79,45.55 70.925,45.415 v1(70.925,44.975)
  Bottom Layer w0.6: 70.55,44.85 70.55,47.175
  Bottom Layer w0.8: U1.6@47.6,55.264 U1.6@47.625,55.264 ; v1(49.375,55.25) 49.361,55.264 U1.6@47.625,55.264 ; v1(50.275,56.2) 49.511,56.964 R4.2@48.2,56.964 48.2,55.839 U1.6@47.625,55.264
pads on no net: CN2.NPTH1 CN2.NPTH2 J1.1 J1.2 J1.6 MIRE-PLACE-4.1 MIRE-PLACE-5.1 MIRE-PLACE-6.1 MIRE-PLACE-7.1 MIRE-PLACE-8.1 MIRE-PLACE-9.1 U6.14

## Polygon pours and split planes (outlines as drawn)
5V on Bottom Layer "5V_L04_P008" (solid, pour order 8): 50.5,53.5 50.5,50.5 51.5,49.5 51.5,46 61.5,46 62.5,47 62.5,49 61,50.5 54,50.5 52.5,52 52.5,53.5
VLED+_SW on Bottom Layer "VLED+_SW_L04_P002" (solid, pour order 2): 46.14,53 46,53.14 46,54 45.5,54 44.5,54 44.5,46 51.5,46 51.5,49.5 49,52 47.5,52 47.336,52.164 46.14,52.164
5V_LCD on Bottom Layer "5V_LCD_L04_P010" (solid, pour order 10): 63,51.9 63,46 63.5,46 64.783,47.283 66.283,47.283 67.625,48.625 67.625,52.575 63.675,52.575
VLED+ on Bottom Layer "VLED+_L04_P000" (solid, pour order 0): 44.5,45.5 63.5,45.5 65,47 68,47 68.5,47.5 70,47.5 70,41.5 68.5,40 44.5,40
AVDD on Bottom Layer "AVDD_L04_P020" (solid, pour order 20): 90,42 90,47.5 90.5,47.5 90.5,44.263 92.707,42.056 98.183,42.056 106.127,50 110.5,50 111,49.5 111,48 110.802,48 110.061,47.259 106.259,47.259 104,45 104.3,44.7 104.3,42.609 103.109,42.609 100,39.5 92.5,39.5
VLED- on Bottom Layer "VLED-_L04_P004" (solid, pour order 4): 47,54.5 52,54.5 52,58 47,58
GND on Bottom Layer "GND_L04_P028" (solid, remove dead copper, pour order 28): 0,117 166,117 166,0 0,0
VGL on Top Layer "VGL_L01_P018" (solid, pour order 18): 89.5,47 89.5,45.456 88.825,44.782 89,44.607 89,44 90.775,44 94.275,47.5 115.325,47.5 125.825,37 131,37 132,38 132,40 131,41 125.5,41 117,49.5 92,49.5 89.29,46.79 89.29,46.5
VGH on Top Layer "VGH_L01_P016" (solid, pour order 16): 87.5,45 87.5,48.5 91.075,52.075 119.925,52.075 126.5,45.5 126.5,43 126,42.5 124.252,42.5 116.923,49.829 91.829,49.829 89,47 89,45.236 88.679,44.915 88.594,45
GND on Top Layer "GND_L01_P024" (solid, remove dead copper, pour order 24): 0,117 166,117 166,0 0,0
VLED- on Signal Layer 1 "VLED-_L02_P012" (solid, remove dead copper, pour order 12): 71.5,47.5 71.5,42.5 58.5,42.5 45.5,55.5 45.5,58.5 47.5,60.5 52.05,60.5 65.05,47.5
5V_LCD on Signal Layer 1 "5V_LCD_L02_P032" (solid, remove dead copper, pour order 32): 65.401,47.925 66.95,47.925 67.65,48.625 67.65,55.725 67.875,55.95 113.675,55.95 120.175,49.45 151.05,49.45 152,50.4 152,59.925 148.425,63.5 67.6,63.5 62.975,58.875 62.975,50.252
VCOM on Signal Layer 1 "VCOM_L02_P014" (solid, remove dead copper, pour order 14): 72,47.5 110.5,47.5 110.5,42.5 72,42.5
3V3 on Signal Layer 1 "3V3_L02_P030" (solid, remove dead copper, pour order 30): 68.025,55.575 113.425,55.575 119.925,49.075 149.925,49.075 149.925,33.5 111,33.5 111,47.228 110.303,47.925 69.175,47.925 68.025,49.075
GND on Signal Layer 1 "GND_L02_P036" (solid, remove dead copper, pour order 36): 0,117 166,117 166,0 0,0
GND on Signal Layer 2 "GND_L03_P034" (solid, remove dead copper, pour order 34): 0,117 166,117 166,0 0,0

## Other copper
Top Layer:
  text "1" at 30.495,3.69 h2.5
  text ".Layer_Name" at 45.688,-24.502 h3
  text ".GTL" at 87.383,-24.502 h3
Signal Layer 1:
  text "2" at 32.245,3.69 h2.5
  text ".Layer_Name" at 45.688,-24.502 h3
  text ".G1" at 87.383,-24.502 h3
Signal Layer 2:
  text "3" at 35.245,3.69 h2.5
  text ".Layer_Name" at 45.688,-24.502 h3
  text ".G2" at 87.383,-24.502 h3
Bottom Layer:
  text "4" at 37.225,3.675 h2.5
  text ".GBL" at 76.18,-24.534 h3
  text ".Layer_Name" at 117.494,-24.534 h3
Multi-Layer:
  pour cut-out: 29.745,5.94 29.745,2.94 38.245,2.94 38.245,5.94

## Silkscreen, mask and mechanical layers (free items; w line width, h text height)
Top Overlay:
  lines w0.12: 45.75,109.5 45.75,116.75 71,116.75 71,109.5 45.75,109.5 ; 91.5,109.5 116.75,109.5 116.75,116.75 91.5,116.75 91.5,109.5
  text "MB1370B" at 7.075,3.7 h3.5
  text "LCD 7\" WVGA" at 70.175,2.65 h4
  text "E" at 105.1,2.05 h10
  text "J" at 42.325,0.525 h16
  text ".Layer_Name" at 45.688,-24.502 h3
  text ".GTO" at 87.383,-24.502 h3
Bottom Overlay:
  lines w0.12: 81.54,8.74 81.54,46.154
  lines w0.254: 61.542,8.74 61.542,25.961 66.546,30.965 68.781,33.2 ; 68.79,33.2 68.79,46.154 ; 94.29,26.139 94.29,46.176 ; 94.308,26.139 96.543,23.904 101.547,18.9 101.547,8.74 ; 130.25,8.742 130.25,28.735 140.25,28.735 ; 130.25,19.01 147.225,19.01 ; 140.225,34.935 140.225,33.76 140.25,33.735 ; 147.225,28.735 140.25,28.735 ; 147.25,8.754 147.25,34.91 ; 147.25,33.735 140.25,33.735 ; 140.25,28.735 140.25,33.735
  text "I" at 161.6,9.875 h15
  text "J" at 19.125,7.525 h16
  text "MB1370B" at 20.325,3.625 h3.5
  text "C" at 129.75,2.05 h8
  text "E" at 84.475,1.575 h10
  text "F" at 63.75,1.275 h10
  text "G" at 50.8,1.075 h10
  text "H" at 112.825,0.35 h15
  text ".GBO" at 76.18,-24.534 h3
  text ".Layer_Name" at 117.494,-24.534 h3
Top Paste:
  text ".Layer_Name" at 45.688,-24.502 h3
  text ".GTP" at 87.383,-24.502 h3
Bottom Paste:
  text ".GBP" at 76.18,-24.534 h3
  text ".Layer_Name" at 117.494,-24.534 h3
Top Solder:
  rectangle: 29.995,3.19 37.995,5.69
  rectangle: 0.25,12.25 10.25,109.25
  region: 165.875,99.25 165.875,109.25 0.25,109.25 0.25,99.25
  region: 165.875,12.25 165.875,22.25 0.25,22.25 0.25,12.25
  rectangle: 155.875,12.25 165.875,109.25
  text ".Layer_Name" at 45.688,-24.502 h3
  text ".GTS" at 87.383,-24.502 h3
Bottom Solder:
  rectangle: 29.995,3.19 37.995,5.69
  text ".GBS" at 76.18,-24.534 h3
  text ".Layer_Name" at 117.494,-24.534 h3
M1-Board Shape:
  lines w0.01: -0.001,116.309 cw(c0.69,116.309) 0.69,117 165.31,117 ; 0,116.31 0,0.69 ccw(c0.691,0.69) 0.691,-0.001 ; 0.69,0 165.31,0 ccw(c165.31,0.691) 166.001,0.691 ; 165.309,117.001 cw(c165.309,116.31) 166,116.31 166,0.69
M2-Board Dimensions:
  text ".Layer_Name" at 45.688,-24.502 h3
  text ".GM2" at 87.383,-24.502 h3
M14-Top Assembly:
  text ".Layer_Name" at 45.688,-24.502 h3
  text ".GM14" at 87.383,-24.502 h3
M15-Bottom Assembly:
  text ".GM15" at 76.18,-24.534 h3
  text ".Layer_Name" at 117.494,-24.534 h3
Drill Drawing:
  drawing of 360 lines, arcs and shapes, not listed
  text "Symbol" at 1.625,156.36 h2.16
  text "Count" at 10.086,156.36 h2.16
  text "Hole Size" at 18.867,156.36 h2.16
  text "Plated" at 35.362,156.36 h2.16
  text "Hole Type" at 42.79,156.36 h2.16
  text "Drill Layer Pair" at 53.604,156.36 h2.16
  text "Via/Pad" at 74.103,156.36 h2.16
  text "Pad Shape" at 82.965,156.36 h2.16
  text "Template" at 94.541,156.36 h2.16
  text "Description" at 125.009,156.36 h2.16
  text "Hole Tolerance (+)" at 136.635,156.36 h2.16
  text "Hole Tolerance (-)" at 154.714,156.36 h2.16
  text "Hole Length" at 172.307,156.36 h2.16
  text "Routed Path Length" at 190.595,156.36 h2.16
  text "1" at 10.086,152.631 h1.8
  text "4,00mm (157,48mil)" at 18.867,152.631 h1.8
  text "NPTH" at 35.362,152.631 h1.8
  text "Slot" at 42.79,152.631 h1.8
  text "Top Layer - Bottom Layer" at 53.604,152.631 h1.8
  text "Pad" at 74.103,152.631 h1.8
  text "Rounded" at 82.965,152.631 h1.8
  text "r3800_400hn400_3800r100m3810_410" at 94.541,152.631 h1.8
  text "38,00mm (1496,06mil)" at 172.307,152.631 h1.8
  text "34,00mm (1338,58mil)" at 190.595,152.631 h1.8
  text "1" at 10.086,148.903 h1.8
  text "4,00mm (157,48mil)" at 18.867,148.903 h1.8
  text "NPTH" at 35.362,148.903 h1.8
  text "Slot" at 42.79,148.903 h1.8
  text "Top Layer - Bottom Layer" at 53.604,148.903 h1.8
  text "Pad" at 74.103,148.903 h1.8
  text "Rounded" at 82.965,148.903 h1.8
  text "r4600_400hn400_4600r100m4610_410" at 94.541,148.903 h1.8
  text "46,00mm (1811,02mil)" at 172.307,148.903 h1.8
  text "42,00mm (1653,54mil)" at 190.595,148.903 h1.8
  text "2" at 10.086,145.175 h1.8
  text "1,00mm (39,37mil)" at 18.867,145.175 h1.8
  text "NPTH" at 35.362,145.175 h1.8
  text "Round" at 42.79,145.175 h1.8
  text "Top Layer - Bottom Layer" at 53.604,145.175 h1.8
  text "Pad" at 74.103,145.175 h1.8
  text "Rounded" at 82.965,145.175 h1.8
  text "c0hn100m105p1000" at 94.541,145.175 h1.8
  text "-" at 172.307,145.175 h1.8
  text "-" at 190.595,145.175 h1.8
  text "4" at 10.086,141.447 h1.8
  text "3,50mm (137,80mil)" at 18.867,141.447 h1.8
  text "PTH" at 35.362,141.447 h1.8
  text "Round" at 42.79,141.447 h1.8
  text "Top Layer - Bottom Layer" at 53.604,141.447 h1.8
  text "Pad" at 74.103,141.447 h1.8
  text "Rounded" at 82.965,141.447 h1.8
  text "(Mixed)" at 94.541,141.447 h1.8
  text "-" at 172.307,141.447 h1.8
  text "-" at 190.595,141.447 h1.8
  text "18" at 10.086,137.719 h1.8
  text "0,30mm (11,81mil)" at 18.867,137.719 h1.8
  text "PTH" at 35.362,137.719 h1.8
  text "Round" at 42.79,137.719 h1.8
  text "Top Layer - Bottom Layer" at 53.604,137.719 h1.8
  text "Via" at 74.103,137.719 h1.8
  text "Rounded" at 82.965,137.719 h1.8
  text "v60h30m0mx0" at 94.541,137.719 h1.8
  text "-" at 172.307,137.719 h1.8
  text "-" at 190.595,137.719 h1.8
  text "804" at 10.086,133.99 h1.8
  text "0,25mm (10,00mil)" at 18.867,133.99 h1.8
  text "PTH" at 35.362,133.99 h1.8
  text "Round" at 42.79,133.99 h1.8
  text "Top Layer - Bottom Layer" at 53.604,133.99 h1.8
  text "Via" at 74.103,133.99 h1.8
  text "Rounded" at 82.965,133.99 h1.8
  text "v60h25m0mx0" at 94.541,133.99 h1.8
  text "-" at 172.307,133.99 h1.8
  text "-" at 190.595,133.99 h1.8
  text "830 Total" at 10.086,130.262 h1.8
  text "Slot definitions :" at 1.625,127.652 h1.8
  text "Routed Path Length" at 13.91,127.652 h1.8
  text "= Calculated from tool start centre position to tool end centre position." at 29.13,127.652 h1.8
  text "Hole Length" at 13.91,126.161 h1.8
  text "= Routed Path Length + Tool Size = Slot length as defined in the PCB layout" at 23.48,126.161 h1.8
  text "PCB SPECIFICATIONS :" at 176.37,113.44 h3
  text "**Plating type :" at 293.42,113.09 h2.5
  text "A.   MATERIAL :" at 176.37,109.44 h3
  text "FR-4" at 214.87,109.44 h3
  text "TG-170" at 231.37,109.44 h3
  text "X  TG-150" at 249.62,109.44 h3
  text "TG-140" at 265.62,109.44 h3
  text "lead Gold" at 300.145,108.615 h2.5
  text "B.   MATERIAL FAMILY :" at 176.37,106.44 h3
  text "N/A" at 214.87,106.44 h3
  text "C.   SOLDERMASK COLOR :" at 176.37,103.44 h3
  text "GREEN" at 214.87,103.44 h3
  text "X  BLUE" at 231.37,103.44 h3
  text "RED" at 249.62,103.44 h3
  text "BLACK" at 265.62,103.44 h3
  text "D.   SILKSCREEN COLOR :" at 176.37,100.44 h3
  text "X  WHITE" at 214.87,100.44 h3
  text "YELLOW" at 231.37,100.44 h3
  text "BLACK" at 249.62,100.44 h3
  text "Blue ink PANTONE 2955" at 265.62,100.44 h3
  text "E.   SURFACE FINISH :" at 176.37,97.44 h3
  text "X  ENIG" at 214.87,97.44 h3
  text "IMMERSION SILVER" at 231.37,97.44 h3
  text "IMMERSION TIN" at 265.62,97.44 h3
  text "HASL" at 214.87,94.44 h3
  text "HASL (PB-FREE)" at 231.37,94.44 h3
  text "GOLDEN FINGER" at 265.62,94.44 h3
  text "F.   IMPEDANCE CONTROL :" at 176.37,91.44 h3
  text "X  NO" at 214.87,91.44 h3
  text "YES  (SEE IMPEDANCE TABLE FOR DETAIL INFORMATION)" at 231.37,91.44 h3
  text "G.   THROUGH VIA :" at 176.37,88.44 h3
  text "PLUG THE VIAS WHICH ARE COVERED WITH SOLDERMASK ONE OR TWO SIDE." at 214.87,88.44 h3
  text "PLUG MATERIAL :" at 214.87,85.44 h3
  text "X  SOLDERMASK" at 240.37,85.44 h3
  text "NON-CONDUCTIVE EPOXY." at 265.62,85.44 h3
  text "H.   STACK-UP :" at 176.37,82.44 h3
  text "SEE LAYER STACK-UP SEQUENCE FOR OVERALL THICKNESS." at 214.87,82.44 h3
  text "Layer" at 178.229,74.35 h2
  text "Name" at 186.603,74.35 h2
  text "Material" at 202.8,74.35 h2
  text "Thickness" at 217.354,74.35 h2
  text "Constant" at 229.309,74.35 h2
  text "Board Layer Stack" at 240.373,74.35 h2
  text "PCB : TYPE 3" at 260.576,73.988 h3
  text "1" at 178.229,70.35 h2
  text "Top Overlay" at 186.603,70.35 h2
  text "ASPECT-RATIO, AXE Z :" at 260.576,68.488 h3
  text "2" at 178.229,66.35 h2
  text "Top Solder" at 186.603,66.35 h2
  text "Solder Resist" at 202.8,66.35 h2
  text "0,015mm" at 217.354,66.35 h2
  text "3,5" at 229.309,66.35 h2
  text "3" at 178.229,62.35 h2
  text "Top Layer" at 186.603,62.35 h2
  text "Copper" at 202.8,62.35 h2
  text "0,042mm" at 217.354,62.35 h2
  text "6:1 to 8:1 / LEVEL \"B\"" at 260.595,61.74 h3
  text "4" at 178.229,58.35 h2
  text "Dielectric 1" at 186.603,58.35 h2
  text "PP-IT-180A" at 202.8,58.35 h2
  text "0,106mm" at 217.354,58.35 h2
  text "4,2" at 229.309,58.35 h2
  text "5" at 178.229,54.35 h2
  text "Signal Layer 1" at 186.603,54.35 h2
  text "Copper" at 202.8,54.35 h2
  text "0,035mm" at 217.354,54.35 h2
  text "MINIMUN PARAMETERS" at 260.82,52.615 h3
  text "6" at 178.229,50.35 h2
  text "Dielectric 2" at 186.603,50.35 h2
  text "FR4" at 202.8,50.35 h2
  text "1,248mm" at 217.354,50.35 h2
  text "4,2" at 229.309,50.35 h2
  text "DEFAULT" at 260.82,47.115 h3
  text "7" at 178.229,46.35 h2
  text "Signal Layer 2" at 186.603,46.35 h2
  text "Copper" at 202.8,46.35 h2
  text "0,035mm" at 217.354,46.35 h2
  text "8" at 178.229,42.35 h2
  text "Dielectric 3" at 186.603,42.35 h2
  text "PP-IT-180A" at 202.8,42.35 h2
  text "0,106mm" at 217.354,42.35 h2
  text "4,2" at 229.309,42.35 h2
  text "TRACKS : 0.120mm           / GAPS : 0.120mm" at 260.82,41.365 h3
  text "9" at 178.229,38.35 h2
  text "Bottom Layer" at 186.603,38.35 h2
  text "Copper" at 202.8,38.35 h2
  text "0,042mm" at 217.354,38.35 h2
  text "10" at 178.229,34.35 h2
  text "Bottom Solder" at 186.603,34.35 h2
  text "Solder Resist" at 202.8,34.35 h2
  text "0,015mm" at 217.354,34.35 h2
  text "3,5" at 229.309,34.35 h2
  text "11" at 178.229,30.35 h2
  text "Bottom Overlay" at 186.603,30.35 h2
  text ".Layer_Name" at 45.688,-24.502 h3
  text ".DRL" at 87.383,-24.502 h3
M20-Top Sheet Box:
  circle w0.254: c123.692,-31.223 r1.3
  region: 123.218,-23.986 107.69,-23.986 106.996,-25.762 105.785,-26.987 104.388,-25.127 104.388,-23.476 105.531,-22.079 106.967,-21.7 123.218,-21.7
  region: 109.214,-32.316 98.458,-32.316 99.452,-29.823 107.309,-29.823 107.758,-29.064 109.967,-31.612
  lines w0.254: 99.452,-29.823 108.244,-29.823 105.177,-26.285 cw(c106.981,-24.341) 107.221,-21.7 123.985,-21.7 123.223,-23.986 ; 102.765,-21.453 cw(c105.192,-22.424) 105.428,-19.821 ; 102.805,-21.421 98.458,-32.316 117.781,-32.316 ccw(c118.03,-29.581) 120.579,-30.601 ; 104.544,-25.355 109.967,-31.612 ; 104.798,-25.355 110.103,-31.477 ; 104.798,-25.101 110.103,-31.223 ; 104.896,-23.986 117.889,-23.986 ; 104.925,-24.974 110.23,-31.096 ; 105.052,-24.847 110.357,-30.969 ; 105.179,-24.72 110.484,-30.842 ; 105.306,-24.593 110.611,-30.715 ; 105.361,-22.641 110.666,-28.762 ; 105.429,-19.821 124.879,-19.821 120.58,-30.599 ; 105.433,-24.466 110.684,-30.525 ; 105.433,-24.212 110.738,-30.334 ; 105.433,-23.958 110.738,-30.08 ; 105.433,-23.069 110.738,-29.191 ; 105.56,-23.831 110.865,-29.953 ; 105.56,-23.45 110.865,-29.572 ; 106.932,-29.836 ccw(c107.037,-29.301) 107.335,-28.844 ; 108.019,-23.973 ccw(c107.993,-24.54) 107.662,-25.002 110.027,-27.731 cw(c108.223,-29.675) 108.956,-32.224 ; 114.3,-32.112 117.189,-23.732 ; 114.522,-32.062 117.391,-23.741 ; 114.649,-32.062 117.518,-23.741 ; 114.903,-32.062 117.772,-23.741 ; 115.157,-32.062 118.026,-23.741 ; 115.411,-32.062 118.28,-23.741 ; 115.665,-32.062 118.534,-23.741 ; 115.919,-32.062 118.788,-23.741 ; 116.173,-32.062 119.042,-23.741 ; 116.427,-32.062 119.296,-23.741 ; 116.636,-32.112 119.525,-23.732 ; 119.525,-23.986 123.218,-23.986 ; 122.549,-23.984 123.311,-21.698 ; 122.715,-23.986 123.477,-21.7 ; 122.969,-23.986 123.731,-21.7
  lines w0.3: 36.688,-31.202 96.688,-31.202 ; 36.688,-26.202 96.688,-26.202 ; 36.688,-21.202 96.688,-21.202 ; 76.688,-36.202 76.688,-21.202 ; 96.688,-36.202 96.688,-16.202 ; 114.3,-32.112 116.636,-32.112 ; 36.688,-36.202 36.688,-16.202 126.688,-16.202 126.688,-36.202 36.688,-36.202
  text "Project: '.Board_Name'" at 37.688,-19.418 h3
  text "Layer:" at 37.688,-24.502 h3
  text "Gerber:" at 77.677,-24.502 h3
  text "Variant: '.VariantName'" at 37.688,-29.502 h3
  text "Ref: '.Board_Reference'" at 77.804,-29.502 h3
  text "R" at 123.184,-31.985 h1.52
  text "Date: '.Board_Document_Date'" at 37.688,-34.502 h3
  text "Rev: '.Board_PCB_Revision'" at 77.747,-34.502 h3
